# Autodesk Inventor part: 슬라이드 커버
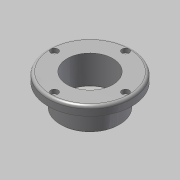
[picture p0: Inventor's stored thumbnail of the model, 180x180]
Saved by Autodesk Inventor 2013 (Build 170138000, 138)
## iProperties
Created: 2015-10
Part Number: 슬라이드 커버
Document SubType Name: Modeling
Designer: mdu
Density: 1 g/cm^3
Material: 강철, 연강
Mass: 76.148 g
Surface Area: 229.996 cm^2
Volume: 76.148 cm^3
Author: mdu
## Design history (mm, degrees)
sketch "스케치1"
  geometry: C1 r 46 at (0, -39.25) reference; C2 r 32.5 at (0, -39.25) reference; 1 further point
  node "참조1"
  node "참조2"
extrude "돌출1" new body sketch "스케치1" distance "d0" = 10; taper "d1" = 0 deg
extrude "돌출2" join sketch "스케치1" distance "d2" = 25; taper "d3" = 0 deg
hole "구멍1" diameter "d6" = 50; stored, may be unused: countersink angle "d10" = 90 deg, drill point angle "d12" = 118 deg; dims "d4" = 10, "d5" = 10, "d7" = 6, "d8" = 4, "d9" = 2, "d11" = 8
sketch "스케치2"
  geometry: C1 r 46 at (0, 0) reference; C2 r 1.621 at (0, 39) reference; C3 r 1.621 at (39, 0) reference; C4 r 1.621 at (0, -39) reference; C5 r 1.621 at (-39, 0) reference; C6 r 33.5 at (0, 0) reference; 1 further point
hole "구멍2" sketch "스케치2" at (0, 39) diameter "d13" = 4.5; stored, may be unused: countersink angle "d17" = 90 deg, drill point angle "d19" = 118 deg; dims "d14" = 6, "d15" = 8, "d16" = 4.4, "d18" = 8
fillet "모깎기1" dims "d23" = 3
chamfer "모따기1" distance "d24" = 1; stored, may be unused: second distance "d25" = 2, angle "d26" = 45 deg
sketch "스케치3"
  geometry: C1 r 25 at (0, 0); C2 r 30 at (0, 0); C3 r 26 at (0, 0) reference; 1 further point
  constraints: 2 centre point, 2 coincident
  dimensions: "d27" = 60 diameter of C2
extrude "돌출3" cut sketch "스케치3" distance "d28" = 3; taper "d29" = 0 deg
chamfer "모따기2" distance "d30" = 1; stored, may be unused: second distance "d31" = 2, angle "d32" = 45 deg
node "솔리드1"
pattern_circular "원형 패턴1" dims angle "d21" = 360 deg
node "참조3"
